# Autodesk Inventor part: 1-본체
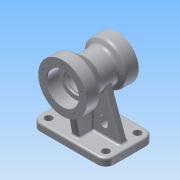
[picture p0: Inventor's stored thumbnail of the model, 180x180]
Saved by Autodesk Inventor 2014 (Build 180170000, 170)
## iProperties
Created: 2015-08
Part Number: 1-본체
Material: 알루미늄 6061
Document SubType Name: Modeling
Designer: study
Density: 2.71 g/cm^3
Appearance: 알루미늄 - 평지
Author: study
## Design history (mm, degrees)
sketch "스케치1"
  geometry: L1 (61, -40)-(-61, -40); L2 (-61, -40)-(-61, 40); L3 (-61, 40)-(61, 40); L4 (61, 40)-(61, -40); L5 (61, -40)-(-61, 40); L6 (-61, -40)-(61, 40); 1 further point
  constraints: 12 end point, 2 midpoint, 2 parallel, 1 horizontal, 1 perpendicular
  dimensions: "d0" = 122 distance of L2.end L3.end; "d1" = 80 distance of L1.end L2.end
extrude "돌출1" new body sketch "스케치1" distance "d2" = 12; taper "d3" = 0 deg
node "작업 평면1"
sketch "스케치2"
  geometry: L1 (-40, 90)-(50, 90); L2 (-40, 0)-(40, 0) reference; L3 (-40, 90)-(-40, 125); L4 (-40, 125)-(-20, 125); L5 (-20, 125)-(-14.804, 116); L6 (-14.804, 116)-(13.315, 116); L7 (13.315, 116)-(30, 130); L8 (30, 130)-(50, 130); L9 (50, 130)-(50, 90); 1 further point
  constraints: 16 end point, 3 parallel, 2 perpendicular, 1 horizontal, 1 vertical alignment
  dimensions: "d5" = 90 distance of L1.start L1.end; "d6" = 90 distance between parallel lines of L2 L1; "d7" = 70 diameter of L4 L1; "d8" = 80 diameter of L8 L1; "d9" = 52 diameter of L6 L1; "d10" = 60 deg angle of L6 L5; "d11" = 40 deg angle of L6 L7; "d12" = 20 distance of L3.end L4.end; "d13" = 20 distance of L7.end L8.end
revolve "회전1" sketch "스케치2" stored, may be unused: angle "d14" = 90 deg
node "작업 평면2"
sketch "스케치3"
  geometry: L1 (61, 12)-(-61, 12) reference; L2 (-51, 12)-(51, 12); L3 (51, 12)-(23.191, 88.404); L4 (-23.191, 88.404)-(23.191, 88.404); L5 (-23.191, 88.404)-(-51, 12); C1 r 35 at (0, 90) reference; 3 further points
  constraints: 8 end point, 2 collinear, 2 midpoint, 1 equal length, 1 parallel, 1 vertical alignment
  dimensions: "d17" = 10 distance of L1.end L2.start; "d20" = 70 deg angle of L1 L5; "d21" = 46.38258 distance of L4.start L3.end
extrude "돌출2" join sketch "스케치3" stored distance "d18" = 12; taper "d19" = 0 deg
sketch "스케치4"
  geometry: L1 (40, 12)-(-40, 12) reference; L2 (-30, 12)-(-30, 75.951); L3 (-30, 75.951)-(41.276, 75.951); L4 (41.276, 75.951)-(30, 12); L5 (-30, 12)-(30, 12); 1 further point
  constraints: 8 end point, 2 perpendicular, 2 point on line, 1 collinear
  dimensions: "d22" = 80 deg angle of L1 L4; "d23" = 10 distance of L2.start L1.end; "d24" = 10 distance of L1.start L4.end; "d25" = 71.27626 distance of L2.end L3.end
extrude "돌출3" join sketch "스케치4" stored distance "d26" = 12; taper "d27" = 0 deg
sketch "스케치5"
  geometry: L1 (47, -26)-(-47, -26); L2 (-47, -26)-(-47, 26); L3 (-47, 26)-(47, 26); L4 (47, 26)-(47, -26); L5 (47, -26)-(-47, 26); L6 (-47, -26)-(47, 26); 5 further points
  constraints: 12 end point, 4 coincident, 2 midpoint, 2 parallel, 1 horizontal, 1 perpendicular
  dimensions: "d28" = 94 distance of L2.end L3.end; "d29" = 52 distance of L1.end L2.end
hole "구멍1" sketch "스케치5" at (-47, 26), (-47, -26), (47, -26), (47, 26) diameter "d30" = 12; stored, may be unused: countersink angle "d34" = 90 deg, drill point angle "d36" = 118 deg; dims "d31" = 6, "d32" = 4, "d33" = 2, "d35" = 8
sketch "스케치6"
  geometry: L1 (-6, 12)-(-51, 12) reference; L2 (18, 36)-(18, 30); L3 (30, 30)-(30, 36); L4 (-30, 36)-(-30, 30); L5 (-18, 30)-(-18, 36); A1 r 6 centre (24, 30) between (18, 30) and (30, 30); A2 r 6 centre (24, 36) between (30, 36) and (18, 36); A3 r 6 centre (-24, 30) between (-30, 30) and (-18, 30); A4 r 6 centre (-24, 36) between (-18, 36) and (-30, 36); 1 further point
  constraints: 8 end point, 8 point on circle, 8 tangent, 4 centre point, 2 parallel, 1 horizontal alignment, 1 perpendicular, 1 vertical
  dimensions: "d37" = 18 distance from line of A1.centre L1; "d38" = 12 distance between parallel lines of L3 L2; "d39" = 18 dimension on A1 A2; "d40" = 12 distance between parallel lines of L5 L4; "d41" = 18 dimension on A3 A4; "d42" = 48 distance of A1.centre A3.centre; "d43" = 24 horizontal distance of A3.centre point (0, 0)
extrude "돌출4" cut sketch "스케치6" stored distance "d44" = 12; taper "d45" = 0 deg
hole "구멍2" diameter "d48" = 38; stored, may be unused: countersink angle "d52" = 90 deg, drill point angle "d54" = 0 deg; dims "d46" = 10, "d47" = 10, "d49" = 6, "d50" = 52, "d51" = 20, "d53" = 23
hole "구멍3" diameter "d57" = 32; stored, may be unused: countersink angle "d61" = 90 deg, drill point angle "d63" = 0 deg; dims "d55" = 10, "d56" = 10, "d58" = 6, "d59" = 40, "d60" = 17, "d62" = 23
sketch "스케치7" dims "d64" = 66
  geometry: C1 r 26 at (0, 0) reference; C2 r 40 at (0, 0) reference; 3 further points
  constraints: 2 vertical alignment, 1 coincident, 2 other
hole "구멍4" sketch "스케치7" at (0, 33) diameter "d65" = 3.242; stored, may be unused: countersink angle "d69" = 82 deg, drill point angle "d71" = 118 deg; dims "d66" = 10, "d67" = 3.023, "d68" = 17, "d70" = 13
sketch "스케치8" dims "d75" = 54
  geometry: C1 r 20 at (0, 0) reference; C2 r 35 at (0, 0) reference; 3 further points
  constraints: 2 vertical alignment, 1 coincident, 2 other
hole "구멍5" sketch "스케치8" at (0, -27) diameter "d76" = 3.242; stored, may be unused: countersink angle "d80" = 82 deg, drill point angle "d82" = 118 deg; dims "d77" = 10, "d78" = 3.023, "d79" = 17, "d81" = 13
chamfer "모따기1" distance "d86" = 1; stored, may be unused: second distance "d87" = 2, angle "d88" = 45 deg
fillet "모깎기1" dims "d89" = 0.3
fillet "모깎기2" dims "d90" = 3, "d91" = 14
fillet "모깎기3" dims "d92" = 3, "d100" = 5
sketch "스케치9"
  geometry: L1 (55.518, 30)-(12, 30) reference; L2 (12, 6)-(12, 30) reference; 2 further points
  constraints: 1 other
  dimensions: "d93" = 24 distance from line of point (36, 14) L2; "d94" = 16 distance from line of point (36, 14) L1
feature "엠보싱1" sketch "스케치9" dims "d0" = 122, "d1" = 80, "d95" = 0.5, "d96" = 0
fillet "모깎기4" dims "d97" = 3
fillet "모깎기5" dims "d98" = 3
fillet "모깎기6" dims "d99" = 3
node "솔리드1"
pattern_circular "원형 패턴1" dims angle "d73" = 360 deg
pattern_circular "원형 패턴2" dims angle "d84" = 360 deg
other parameters: "d4" = 0, "d15" = 0
